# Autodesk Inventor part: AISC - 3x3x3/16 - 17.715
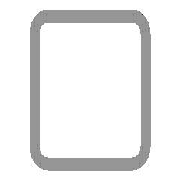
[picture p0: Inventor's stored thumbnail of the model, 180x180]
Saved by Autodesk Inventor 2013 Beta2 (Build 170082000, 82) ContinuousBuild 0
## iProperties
_CCFamilyMember: 9
_CCFamilyDisplayName: ANSI AISC (Square) - Tube
_FrameMemberDoc: Frame Member File
_Version: 15.0.0
_GetPNFromCC: 1
Created: 2010-11
Part Number: AISC - 3x3x3/16 - 17.715
Material: Steel, Mild
Description: Tube
Document SubType Name: Modeling
Standard: ANSI
Designer: Beta-8540w
Standards Organization: ANSI
Language: en-US
Size Designation: 3x3x3/16
Categories: <MemberInstance><Categories><Category DisplayName="Structural Shapes" InternalName="089c4875-fa83-4c05-b084-43b9cc11f5ed" Mnemonic="GRDR"><CategoryParameter Dis
Stock Number: 3x3x3/16
Density: 7.86 g/cm^3
IsCustomPart: 1
G_L: 17.715 in
G_W: 3.000 in
G_H: 3.000 in
Author: Beta-8540w
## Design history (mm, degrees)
node "Start plane"
node "End plane"
sketch "Sketch"
  geometry: L1 (-38.1, -28.575)-(-38.1, 28.575); L2 (-28.575, 38.1)-(28.575, 38.1); L3 (38.1, 28.575)-(38.1, -28.575); L4 (28.575, -38.1)-(-28.575, -38.1); L5 (-28.575, 33.337)-(28.575, 33.338); L6 (33.338, 28.575)-(33.338, -28.575); L7 (28.575, -33.337)-(-28.575, -33.338); L8 (-33.338, -28.575)-(-33.338, 28.575); L9 (0, 56.102)-(0, -56.102) reference; L10 (-56.102, 0)-(56.102, 0) reference; A1 r 9.525 centre (-28.575, -28.575) between (-38.1, -28.575) and (-28.575, -38.1); A2 r 9.525 centre (-28.575, 28.575) between (-28.575, 38.1) and (-38.1, 28.575); A3 r 9.525 centre (28.575, 28.575) between (38.1, 28.575) and (28.575, 38.1); A4 r 9.525 centre (28.575, -28.575) between (28.575, -38.1) and (38.1, -28.575); A5 r 4.763 centre (-28.575, 28.575) between (-28.575, 33.337) and (-33.338, 28.575); A6 r 4.763 centre (28.575, 28.575) between (33.338, 28.575) and (28.575, 33.338); A7 r 4.763 centre (28.575, -28.575) between (28.575, -33.337) and (33.338, -28.575); A8 r 4.763 centre (-28.575, -28.575) between (-33.338, -28.575) and (-28.575, -33.338)
  constraints: 16 end point, 16 point on circle, 8 centre point, 8 tangent, 4 parallel, 3 equal radius, 2 perpendicular, 7 other
  dimensions: "d10" = 76.2 distance between parallel lines of L2 L4 (= G_H); "d11" = 76.2 distance between parallel lines of L1 L3 (= G_W); "d12" = 4.7625 distance between parallel lines of L3 L6 (= G_T); "d15" = 38.1 distance between parallel lines of L2 L10 (= 0.5 x d10); "d16" = 38.1 distance between parallel lines of L9 L3 (= 0.5 x d11); "d17" = 9.525 radius of A1 (= G_IR)
extrude "Body" new body sketch "Sketch" stored distance "d3" = 449.97309 (= G_L); taper "d4" = 0 deg
node "Driven Length"
  sketch "Sketch3"
    geometry: L1 (0, 0)-(10, 0) reference
    constraints: 2 end point, 1 horizontal
  workplane "Work Plane3"
  sketch "Sketch4"
    geometry: L1 (-2, 0)-(12, 0) reference; L2 (-2, 449.973)-(12, 449.973) reference
    dimensions: "d19" = 449.97309 distance between parallel lines of L1 L2 (derived)
body "Solid1"
other parameters: "G_W" = 76.2 [user parameter; used in 1 equation term], "G_H" = 76.2 [user parameter; used in 1 equation term], "G_T" = 4.7625 [user parameter; used in 1 equation term], "G_IR" = 9.525 [user parameter; used in 1 equation term], "G_L" = 449.97309 (= d19) [user parameter; used in 1 equation term], "G_OFFSET_START" = 0 [user parameter; used in 1 equation term], "G_OFFSET_END" = 0 [user parameter; used in 1 equation term], "d13" = 0 (computed from G_OFFSET_START), "d14" = 449.97309 (= G_OFFSET_END + B_L), "B_L" = 449.97309 [user parameter; used in 1 equation term], "d18" = 90 deg
